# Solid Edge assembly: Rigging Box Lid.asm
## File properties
Author: m_hel
Template: Iso Metric Assembly.asm
Last saved by: m_hel
Revision: 8
Application: Solid Edge
Username: m_hel
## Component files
Rigging Storage Lid.par
Lid Hinge.asm
Lid Hinge_mir.asm
Lid Handle.asm
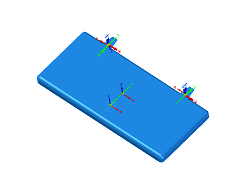
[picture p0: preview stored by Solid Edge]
